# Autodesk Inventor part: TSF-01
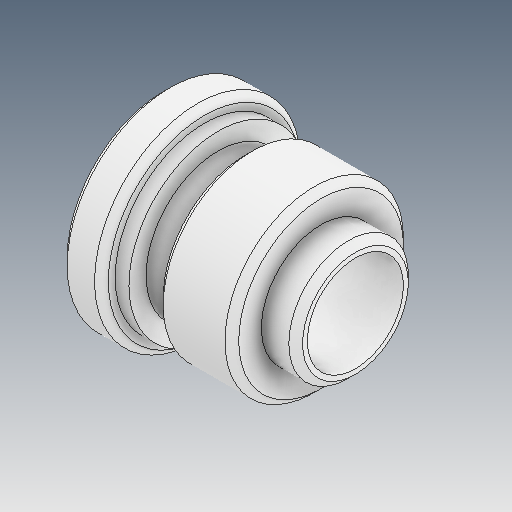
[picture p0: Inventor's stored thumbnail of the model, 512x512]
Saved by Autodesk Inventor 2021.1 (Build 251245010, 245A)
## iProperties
Created: 2021-05
Part Number: TSF-01
Material: Ogólny
Document SubType Name: Modeling
Designer: user
Density: 1 g/cm^3
Appearance: Domyślna
Author: user
Revision Number: ÈÎºÎ
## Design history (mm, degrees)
feature "ÊäÈë1"
node "Bryła1"
